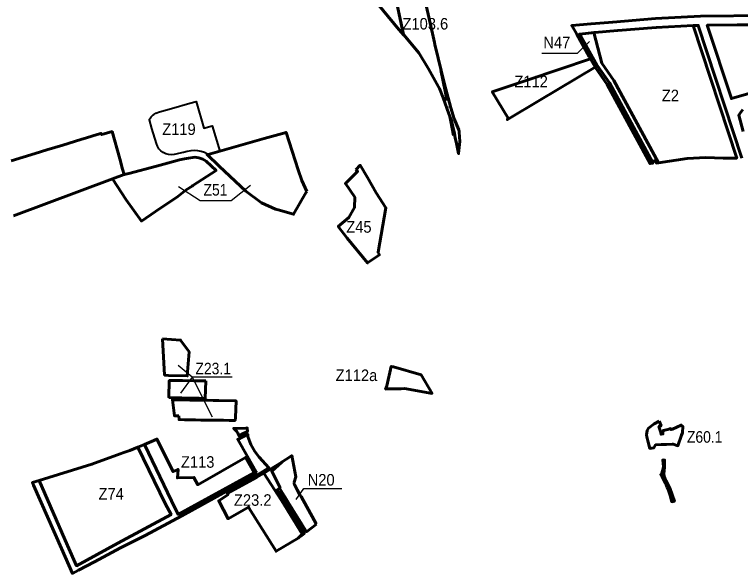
# Model space of a CAD drawing. Extents: x -650277 to -643422, y -1073980 to -1066720.
# Drawn here: x -648765 to -647259, y -1070690 to -1069529 of the extents above; entities that cross this region are included whole.
import ezdxf

# ---------------------------------------------------------------- set-up
doc = ezdxf.new("R2010")
doc.units = 0
doc.header["$LTSCALE"] = 9.6
doc.header["$PDMODE"] = 32
doc.header["$PDSIZE"] = 4.8
doc.linetypes.add('DOT_DASHED', pattern=[7.7, 5, -1.2, 0.3, -1.2])
for name, color, linetype, lineweight in [('1', 7, 'Continuous', 60), ('15', 7, 'Continuous', 60), ('17', 7, 'Continuous', 60), ('24', 7, 'Continuous', 60), ('3', 7, 'Continuous', 60), ('35', 7, 'Continuous', 60), ('36', 7, 'Continuous', 60), ('40', 7, 'Continuous', 60), ('42', 7, 'Continuous', 60), ('61', 7, 'Continuous', 60), ('62', 7, 'DOT_DASHED', 40), ('63', 7, 'Continuous', 25), ('7', 7, 'Continuous', 60), ('9', 7, 'Continuous', 60)]:
    doc.layers.add(name, color=color, linetype=linetype, lineweight=lineweight)

msp = doc.modelspace()

# ---------------------------------------------------------------- linework, layer by layer
at = {"layer": '1'}
for points in [[(-647356.899, -1069552.034), (-647433.779, -1069556.106), (-647433.779, -1069556.106), (-647513.66, -1069562.249), (-647514.067, -1069562.282), (-647560.836, -1069566.036), (-647563.104, -1069566.28)], [(-647369.3, -1069828.22), (-647330.46, -1069825.51), (-647294.38, -1069826.88), (-647270.09, -1069827.02), (-647266.581, -1069827.042), (-647356.899, -1069552.034)], [(-647563.104, -1069566.28), (-647546.777, -1069629.901), (-647521.943, -1069665.763)], [(-647521.943, -1069665.763), (-647428.993, -1069836.714), (-647369.3, -1069828.22)], [(-648368.25, -1070289.71), (-648372.1, -1070289.59), (-648380.97, -1070289.44), (-648392.94, -1070289.25), (-648416.93, -1070288.85), (-648420.39, -1070288.79), (-648428.98, -1070288.92), (-648435.93, -1070288.95), (-648444.15, -1070289.16), (-648444.85, -1070324.47)], [(-648444.85, -1070324.47), (-648444.85, -1070324.47), (-648430.02, -1070324.76), (-648418.1, -1070325), (-648406.09, -1070325.23), (-648394.08, -1070325.47), (-648382.06, -1070325.7), (-648370.07, -1070325.94), (-648368.25, -1070289.71)], [(-648307.13, -1070365.57), (-648305.47, -1070331.23), (-648341.46, -1070330.48), (-648353.32, -1070330.23), (-648365.35, -1070329.98), (-648389.43, -1070329.58), (-648401.41, -1070329.39), (-648413.45, -1070329.19), (-648425.43, -1070329), (-648437.65, -1070328.8), (-648433.46, -1070361.94), (-648424.31, -1070362.21)], [(-648424.31, -1070362.21), (-648424.05, -1070370), (-648412.75, -1070370.28), (-648401.35, -1070370.5), (-648390.06, -1070370.72), (-648378.73, -1070370.94), (-648367.67, -1070371.16), (-648355.67, -1070371.28), (-648343.67, -1070371.41), (-648331.67, -1070371.53), (-648319.67, -1070371.65), (-648307.67, -1070371.78), (-648307.13, -1070365.57)]]:
    msp.add_lwpolyline(points, dxfattribs=at)
for points in [[(-647251.002, -1069695.852), (-647219.628, -1069686.746), (-647203.374, -1069684.716), (-647139.649, -1069679.961), (-647113.255, -1069679.966), (-647082.761, -1069681.399), (-647083.356, -1069551.018), (-647140.247, -1069549.071), (-647158.572, -1069549.252), (-647211.05, -1069549.77), (-647227.623, -1069550.23), (-647327.682, -1069551.263), (-647277.71, -1069703.421)], [(-648458.28, -1070202.26), (-648454.038, -1070277.767), (-648446.18, -1070278.15), (-648406.8, -1070279.32), (-648403.04, -1070229.15), (-648420.7, -1070204.96)]]:
    msp.add_lwpolyline(points, close=True, dxfattribs=at)
at = {"layer": '1', "lineweight": 40}
msp.add_lwpolyline([(-648339.05, -1069812.45), (-648363.68, -1069819.31), (-648371.21, -1069815.56), (-648378.1, -1069813.29), (-648385.21, -1069811.91), (-648392.45, -1069811.44), (-648399.68, -1069811.88), (-648406.84, -1069813.23), (-648414.657, -1069815.246), (-648415.99, -1069815.59), (-648430.881, -1069818.663), (-648433.97, -1069819.3), (-648439.89, -1069819.97), (-648445.8, -1069819.51), (-648451.53, -1069817.98), (-648456.88, -1069815.39), (-648461.64, -1069811.86), (-648465.67, -1069807.49), (-648468.82, -1069802.44), (-648470.97, -1069796.9), (-648480.267, -1069765.316), (-648485.44, -1069747.39), (-648485.14, -1069746.55), (-648483.274, -1069743.777), (-648481.79, -1069741.57), (-648477.39, -1069737.44), (-648476.022, -1069736.525), (-648472.4, -1069734.1), (-648464.45, -1069730.89), (-648439.8, -1069724.19), (-648401.288, -1069713.154), (-648388.631, -1069709.738), (-648372.639, -1069765.241), (-648355.015, -1069760.287)], close=True, dxfattribs=at)
at = {"layer": '15'}
for points in [[(-647204.293, -1069530.647), (-647341.697, -1069532.602), (-647434.969, -1069537.141), (-647523.931, -1069544.499), (-647568.792, -1069548.21), (-647608.81, -1069551.868), (-647598.735, -1069570.026), (-647573.15, -1069616.16), (-647570.37, -1069621.18), (-647560.36, -1069638.39), (-647535.588, -1069674.163), (-647446.322, -1069838.338), (-647441.19, -1069837.6), (-647440.46, -1069836.558), (-647530.471, -1069671.013), (-647555.266, -1069635.207), (-647592.199, -1069569.411), (-647560.836, -1069566.036), (-647514.067, -1069562.282), (-647513.66, -1069562.249), (-647433.779, -1069556.106), (-647433.779, -1069556.106), (-647356.899, -1069552.034), (-647346.554, -1069551.486), (-647256.034, -1069827.107)], [(-647256.061, -1069697.32), (-647277.71, -1069703.421), (-647327.682, -1069551.263), (-647204.208, -1069549.647)], [(-647253.45, -1069771.95), (-647262.46, -1069738.25), (-647259.11, -1069733.52), (-647253.97, -1069726.27)], [(-648213.87, -1070524.8), (-648221.359, -1070516.349), (-648215.48, -1070512.59), (-648214.34, -1070511.86), (-648231.53, -1070476.99), (-648210.48, -1070458.42), (-648247.67, -1070481.57), (-648211, -1070538)], [(-648176.54, -1070616.09), (-648169.28, -1070610.49), (-648163.8, -1070606.27), (-648213.87, -1070524.8)], [(-648211, -1070538), (-648168.575, -1070607.847), (-648176.54, -1070616.09)]]:
    msp.add_lwpolyline(points, dxfattribs=at)
for points in [[(-648303.705, -1070395.035), (-648302.028, -1070398.436), (-648299.32, -1070403.93), (-648295.18, -1070401.23), (-648281.907, -1070394.762), (-648282.582, -1070387.276), (-648284.37, -1070387.85), (-648310.275, -1070388.476)], [(-648550.72, -1070626.869), (-648636.757, -1070673.431), (-648655.178, -1070631.294), (-648714.161, -1070496.376), (-648728.255, -1070500.709), (-648725.835, -1070506.221), (-648668.207, -1070637.453), (-648645.331, -1070689.546), (-648632.652, -1070682.82), (-648599.66, -1070665.32), (-648545.76, -1070636.22), (-648494.04, -1070610.73), (-648417.855, -1070569.57), (-648325.21, -1070518.84), (-648264.56, -1070486.34), (-648260.57, -1070484.2), (-648237.475, -1070470.361), (-648257.96, -1070448.17), (-648266.416, -1070436.404), (-648274.808, -1070421.647), (-648280.974, -1070405.11), (-648281.388, -1070400.523), (-648302.01, -1070411.05), (-648282.01, -1070446.35), (-648263.859, -1070478.393), (-648425.835, -1070567.021), (-648439.409, -1070538.729), (-648495.666, -1070421.476), (-648509.227, -1070426.957), (-648452.97, -1070544.21), (-648440.531, -1070567.236)], [(-647404.96, -1070527.57), (-647401.35, -1070540.59), (-647395.75, -1070539.47), (-647404.879, -1070514.114), (-647413.552, -1070496.671), (-647417.297, -1070487.185), (-647418.038, -1070482.516), (-647417.482, -1070476.846), (-647416.37, -1070468.064), (-647416.148, -1070454.055), (-647418.49, -1070453.76), (-647420.13, -1070454.78), (-647420.22, -1070454.02), (-647418.41, -1070468.21), (-647420.74, -1070476.57), (-647422.285, -1070480.931), (-647424.226, -1070484.029), (-647422.19, -1070487.75), (-647414.6, -1070502.16), (-647410.86, -1070510.68), (-647408.82, -1070515.49)]]:
    msp.add_lwpolyline(points, close=True, dxfattribs=at)
msp.add_point((-648213.87, -1070524.8), dxfattribs=at)
at = {"layer": '17'}
msp.add_lwpolyline([(-647427.8, -1070373.32), (-647437.76, -1070378.66), (-647449.69, -1070387.83), (-647452.17, -1070392.38), (-647453.71, -1070401.81), (-647453.35, -1070406.09), (-647450.51, -1070416.96), (-647446.93, -1070429.99), (-647438.45, -1070428.47), (-647434.85, -1070422.64), (-647423.38, -1070421.87), (-647412.51, -1070421.5), (-647400.41, -1070421.08), (-647398.21, -1070421.15), (-647388.6, -1070424.24), (-647381.11, -1070402.45), (-647379.3, -1070397.57), (-647378.49, -1070383.91), (-647381.65, -1070381.45), (-647400.22, -1070389.64), (-647403.27, -1070390.91), (-647404, -1070388.84), (-647409.36, -1070390.24), (-647419.08, -1070392.52), (-647419.68, -1070399.59), (-647423.58, -1070400.59), (-647424.54, -1070394.78), (-647425.99, -1070390.47), (-647427.96, -1070384.64), (-647423.57, -1070382.64)], close=True, dxfattribs=at)
msp.add_lwpolyline([(-647427.8, -1070373.32), (-647437.76, -1070378.66), (-647449.69, -1070387.83), (-647452.17, -1070392.38), (-647453.71, -1070401.81), (-647453.35, -1070406.09), (-647450.51, -1070416.96), (-647446.93, -1070429.99), (-647438.45, -1070428.47), (-647434.85, -1070422.64), (-647423.38, -1070421.87), (-647412.51, -1070421.5), (-647400.41, -1070421.08), (-647398.21, -1070421.15), (-647388.6, -1070424.24), (-647381.11, -1070402.45), (-647379.3, -1070397.57), (-647378.49, -1070383.91), (-647381.65, -1070381.45), (-647400.22, -1070389.64), (-647403.27, -1070390.91), (-647404, -1070388.84), (-647409.36, -1070390.24), (-647419.08, -1070392.52), (-647419.68, -1070399.59), (-647423.58, -1070400.59), (-647424.54, -1070394.78), (-647425.99, -1070390.47), (-647427.96, -1070384.64), (-647423.57, -1070382.64)], close=True, dxfattribs=at)
at = {"layer": '24'}
msp.add_lwpolyline([(-648495.666, -1070421.476), (-648439.409, -1070538.729), (-648425.835, -1070567.021), (-648267.801, -1070480.55), (-648285.75, -1070448.49), (-648385.085, -1070505.351), (-648393.14, -1070490.07), (-648427.41, -1070491.08), (-648426.05, -1070473.34), (-648436.22, -1070478.01), (-648469.77, -1070410.47), (-648481.18, -1070415.62)], close=True, dxfattribs=at)
at = {"layer": '3'}
msp.add_lwpolyline([(-648767.83, -1069946.87), (-648562.242, -1069870.301), (-648537.86, -1069861.22), (-648541.06, -1069849.78), (-648546.97, -1069828.68), (-648562.87, -1069771.85), (-648579.63, -1069776.66), (-648584.65, -1069778.1), (-648586.09, -1069775.75), (-648593.59, -1069778.06), (-648615.88, -1069784.93), (-648627.99, -1069788.67), (-648665.05, -1069799.99), (-648698.31, -1069810.16), (-648722.24, -1069817.54), (-648772.48, -1069832.83)], dxfattribs=at)
for points in [[(-648159.1, -1069896.39), (-648169.15, -1069873.81), (-648176.78, -1069851.74), (-648201.83, -1069773.86), (-648247.27, -1069786.64), (-648251.94, -1069787.95), (-648339.05, -1069812.45), (-648363.68, -1069819.31), (-648365.81, -1069819.9), (-648340.38, -1069843.78), (-648285.62, -1069895.71), (-648253.13, -1069919.7), (-648223.99, -1069932.96), (-648218.245, -1069934.595), (-648186.268, -1069943.697), (-648160.04, -1069897.73)], [(-648470.79, -1069843.51), (-648528.11, -1069858.73), (-648537.86, -1069861.22), (-648562.242, -1069870.301), (-648533.79, -1069913.49), (-648502.048, -1069957.969), (-648472.6, -1069937.81), (-648426.82, -1069906.88), (-648409.44, -1069893.25), (-648396.87, -1069885.43), (-648395.03, -1069884.22), (-648347.06, -1069853), (-648367.64, -1069833.35), (-648374.89, -1069829.22), (-648382.8, -1069826.55), (-648391.08, -1069825.45), (-648408.45, -1069827.83), (-648412.74, -1069828.72), (-648422.75, -1069830.78), (-648435.53, -1069834.44), (-648447.98, -1069837.44)], [(-648057.11, -1069851.12), (-648053.61, -1069854.64), (-648078.54, -1069880.01), (-648059.32, -1069908.27), (-648059.5, -1069929.52), (-648071.58, -1069950.39), (-648093.67, -1069969.42), (-648074.96, -1069993.46), (-648032.85, -1070044.73), (-648008.18, -1070028.25), (-648010.44, -1070023.66), (-648010.94, -1070022.65), (-647994.71, -1069930.53), (-648015.11, -1069898.98), (-648032.94, -1069867.46), (-648048.08, -1069841.95)]]:
    msp.add_lwpolyline(points, close=True, dxfattribs=at)
at = {"layer": '35'}
msp.add_lwpolyline([(-647740.74, -1069744.24), (-647742.36, -1069746.93), (-647674.901, -1069706.701), (-647560.36, -1069638.39), (-647570.37, -1069621.18), (-647701.61, -1069665.279), (-647774.11, -1069689.64)], close=True, dxfattribs=at)
at = {"layer": '36'}
for points in [[(-647962.82, -1070305.9), (-647956.36, -1070305.77), (-647898.82, -1070315.51), (-647921.51, -1070276.76), (-647979.24, -1070260.71), (-647983.6, -1070259.5), (-647992.71, -1070300.01), (-647995.46, -1070306.55), (-647991.12, -1070306.46)], [(-648636.757, -1070673.431), (-648550.72, -1070626.869), (-648440.531, -1070567.236), (-648452.97, -1070544.21), (-648509.227, -1070426.957), (-648526.28, -1070433.85), (-648538.611, -1070438.388), (-648546.377, -1070441.246), (-648604.92, -1070462.79), (-648714.161, -1070496.376), (-648655.178, -1070631.294)], [(-648636.757, -1070673.431), (-648550.72, -1070626.869), (-648440.531, -1070567.236), (-648452.97, -1070544.21), (-648509.227, -1070426.957), (-648526.28, -1070433.85), (-648538.611, -1070438.388), (-648546.377, -1070441.246), (-648604.92, -1070462.79), (-648714.161, -1070496.376), (-648655.178, -1070631.294)]]:
    msp.add_lwpolyline(points, close=True, dxfattribs=at)
at = {"layer": '40'}
msp.add_line((-648214.34, -1070511.86), (-648215.48, -1070512.59), dxfattribs=at)
for points in [[(-648186.441, -1070501.65), (-648186.088, -1070501.313), (-648184.791, -1070500.073), (-648181.386, -1070488.724), (-648189.93, -1070444.71), (-648194.56, -1070447.8), (-648194.56, -1070447.799), (-648209.82, -1070457.98), (-648210.48, -1070458.42), (-648231.53, -1070476.99), (-648214.34, -1070511.86)], [(-648166.63, -1070537.28), (-648170.72, -1070529.92), (-648172.96, -1070525.9), (-648178.7, -1070515.58), (-648184.54, -1070505.07), (-648186.441, -1070501.65)], [(-648215.48, -1070512.59), (-648210.19, -1070521.07), (-648203.83, -1070531.25), (-648197.59, -1070541.27), (-648190.71, -1070552.3), (-648182.98, -1070564.68), (-648171.02, -1070583.86), (-648159.23, -1070602.75), (-648138.93, -1070587.1)], [(-648138.93, -1070587.1), (-648140.05, -1070585.09), (-648166.63, -1070537.28)]]:
    msp.add_lwpolyline(points, dxfattribs=at)
at = {"layer": '42'}
msp.add_lwpolyline([(-647555.266, -1069635.207), (-647530.471, -1069671.013), (-647440.46, -1069836.558), (-647437.46, -1069832.27), (-647433.32, -1069837.33), (-647428.993, -1069836.714), (-647521.943, -1069665.763), (-647546.777, -1069629.901), (-647563.104, -1069566.28), (-647592.199, -1069569.411)], close=True, dxfattribs=at)
at = {"layer": '61'}
for points in [[(-648034.421, -1069167.61), (-648034.421, -1069167.61), (-648033, -1069189), (-648015, -1069300), (-648010.092, -1069322.087), (-647980.331, -1069465.915), (-647958.34, -1069570.699), (-647925.99, -1069608.57), (-647906.16, -1069641.48), (-647885.665, -1069678.788), (-647885.663, -1069678.794), (-647883.51, -1069682.71), (-647875.82, -1069701.85), (-647875.82, -1069701.85), (-647864.19, -1069735.12), (-647858.44, -1069749.43), (-647852.63, -1069775.7), (-647850.66, -1069785.74), (-647849.165, -1069793.367)], [(-647852.78, -1069745.71), (-647859.722, -1069722.428), (-647872.87, -1069673.56), (-647892.79, -1069591.06), (-647892.789, -1069591.06), (-647893.75, -1069587.08), (-647922.04, -1069459.71), (-647925.16, -1069445.68), (-647928.41, -1069431.03), (-647945.28, -1069355.1), (-647956.27, -1069311.58), (-647962.2, -1069290.88)], [(-647841.402, -1069792.351), (-647842.489, -1069773.282), (-647842.622, -1069770.956), (-647843.337, -1069769.013), (-647843.443, -1069768.293), (-647852.78, -1069745.71)], [(-647849.165, -1069793.367), (-647843.74, -1069817.63), (-647841.402, -1069792.351)]]:
    msp.add_lwpolyline(points, dxfattribs=at)
at = {"layer": '62'}
msp.add_lwpolyline([(-647855.282, -1069780.988), (-647871.488, -1069692.474), (-647887.497, -1069616.134), (-647904.75, -1069533.925), (-647921.593, -1069453.674)], dxfattribs=at)
at = {"layer": '63'}
for q in [(-648421, -1070315), (-648355.27, -1070364.25)]:
    msp.add_line((-648397, -1070282), q, dxfattribs=at)
for points in [[(-647671, -1069609), (-647597, -1069609), (-647572, -1069585)], [(-648425, -1069886), (-648380, -1069915), (-648316, -1069915), (-648276, -1069883)], [(-648314, -1070282), (-648397, -1070282), (-648426, -1070258)], [(-648181, -1070536), (-648165, -1070513), (-648086, -1070513)]]:
    msp.add_lwpolyline(points, dxfattribs=at)
at = {"layer": '7'}
msp.add_lwpolyline([(-648247.67, -1070481.57), (-648262.69, -1070489.67), (-648323.59, -1070522.48), (-648322.18, -1070525.44), (-648341.41, -1070538.42), (-648322.16, -1070575.76), (-648289.22, -1070557.15), (-648279.736, -1070551.783), (-648278.89, -1070553.14), (-648222.58, -1070643.48), (-648176.54, -1070616.09), (-648168.575, -1070607.847), (-648211, -1070538)], close=True, dxfattribs=at)
at = {"layer": '9'}
msp.add_lwpolyline([(-648015, -1069300), (-648033, -1069189), (-648034.421, -1069167.61), (-648071.9, -1069142.06), (-648073.66, -1069140.86), (-648141.92, -1069121.66), (-648171.14, -1069122.83), (-648207.77, -1069129.95), (-648209.89, -1069130.36), (-648226.51, -1069136.57), (-648248.14, -1069144.65), (-648268.87, -1069158.61), (-648270.92, -1069159.99), (-648275.19, -1069162.87), (-648280.1, -1069166.97), (-648203.01, -1069264.73), (-648127.77, -1069361.38), (-648068.71, -1069436.57), (-647967.53, -1069559.94), (-647958.214, -1069571.3), (-647980.331, -1069465.915), (-648010.092, -1069322.087)], close=True, dxfattribs=at)

# ---------------------------------------------------------------- texts
at = {"layer": '1', "width": 0.95}
msp.add_text('Z119', height=24, dxfattribs=at).set_placement((-648458.914, -1069779.092))
at = {"layer": '63'}
for s, width, p in [('Z103.6', 0.95, (-647960.304, -1069560.198)), ('N47', 0.95, (-647668, -1069599)), ('Z112', 0.95, (-647728, -1069680)), ('Z2', 0.95, (-647422, -1069709)), ('Z51', 0.9, (-648373.214, -1069904.865)), ('Z45', 0.95, (-648077, -1069982)), ('Z23.1', 0.9, (-648390, -1070276)), ('Z112a', 0.95, (-648099, -1070290)), ('Z60.1', 0.9, (-647370, -1070418)), ('Z113', 0.95, (-648420, -1070470)), ('N20', 0.95, (-648157, -1070507)), ('Z74', 0.95, (-648591, -1070536)), ('Z23.2', 0.95, (-648310, -1070549))]:
    msp.add_text(s, height=24, dxfattribs=dict(at, width=width)).set_placement(p)

doc.saveas('drawing.dxf')
